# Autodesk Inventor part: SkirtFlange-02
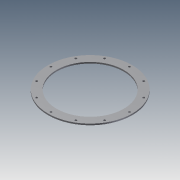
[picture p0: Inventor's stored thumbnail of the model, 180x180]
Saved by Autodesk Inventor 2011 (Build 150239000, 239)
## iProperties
Created: 2010-06
Part Number: SkirtFlange-02
Document SubType Name: Modeling
Designer: mklassen
Density: 1 g/cm^3
OD: 24.000 in
THK: 0.500 in
WDT: 3.000 in
BHN: 12.000 ul
BHD: 0.750 in
BCD: 14.000 in
Author: mklassen
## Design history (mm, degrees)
sketch "skSkirtFlange"
  geometry: C1 r 304.8 at (0, 0); C2 r 381 at (0, 0); 1 further point
  constraints: 2 centre point, 2 coincident
  dimensions: "d0" = 76.2 radial gap between concentric circles of C2 C1 (derived); "d1" = 609.6 diameter of C1 (derived)
extrude "SkirtFlange" new body sketch "skSkirtFlange" stored distance "d2" = 12.7 (derived); taper "d3" = 0 deg
sketch "skBoltHole"
  geometry: C1 r 304.8 at (0, 0) reference; 2 further points
  constraints: 1 coincident, 1 vertical alignment
  dimensions: "d7" = 355.6 distance of point (0, 355.6) point (0, 0) (= BCD)
hole "BoltHole" sketch "skBoltHole" at (0, 355.6) diameter "d8" = 19.05 (derived); stored, may be unused: countersink angle "d12" = 82 deg, drill point angle "d14" = 118 deg; dims "d9" = 19.05, "d10" = 9.525, "d11" = 6.35, "d13" = 25.4
pattern_circular "BoltCircle" dims angle "d16" = 360 deg
body "Solid1"
other parameters: "BCD" = 355.6 [user parameter; used in 2 equation terms], "d4" = 0, "d5" = 0, "d6" = 0
